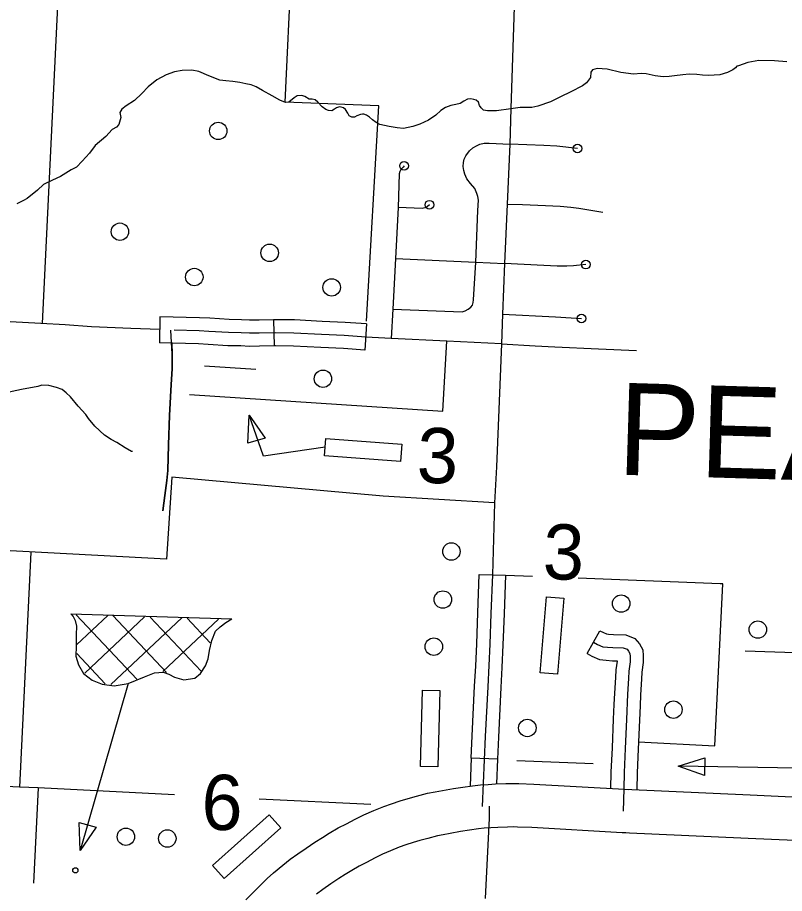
# Model space of a CAD drawing. Extents: x 653372 to 905732, y 627442 to 787275.
# Drawn here: x 679957 to 684356, y 774006 to 779033 of the extents above; entities that cross this region are included whole.
import ezdxf

# ---------------------------------------------------------------- set-up
doc = ezdxf.new("R2010")
doc.units = 0
for name, color, linetype in [('10', 7, 'Continuous'), ('31', 7, 'Continuous'), ('32', 7, 'Continuous'), ('33', 7, 'Continuous'), ('34', 7, 'Continuous'), ('35', 7, 'Continuous'), ('4', 7, 'Continuous'), ('45', 7, 'Continuous'), ('5', 7, 'Continuous'), ('56', 7, 'Continuous'), ('57', 7, 'Continuous'), ('6', 7, 'Continuous')]:
    doc.layers.add(name, color=color, linetype=linetype)

msp = doc.modelspace()

# ---------------------------------------------------------------- linework, layer by layer
at = {"layer": '10'}
for points in [[(681267.1, 773968.3), (681325, 774029.1), (681389.3, 774092.1), (681425.8, 774123.9), (681478.6, 774168.1), (681521.4, 774201.8), (681564.1, 774232.3), (681612.1, 774265.9), (681661.5, 774299.7), (681706, 774327.7), (681744.7, 774350.9), (681795.4, 774381.5), (681843.4, 774405.8), (681893.7, 774432.5), (681943.7, 774457.4), (682000.1, 774482.2), (682057.2, 774504.6), (682101.5, 774520.9), (682151.1, 774537.3), (682198.4, 774551.2), (682246, 774563.4), (682309.1, 774580.4), (682352.7, 774589), (682395.1, 774596.1), (682458, 774607.4), (682511.5, 774615.3), (682567.1, 774624.2), (682613.2, 774629.3), (682657.3, 774631.3), (682698.4, 774634), (682758.1, 774636.2), (682799, 774637.6), (682832.3, 774636.6), (682918.8, 774633.2), (683438.8, 774603.7), (683460.1, 774602.5)], [(683438.8, 774603.7), (684159.3, 774571.5), (684560.8, 774553.4), (684637.6, 774550.3), (684786.5, 774543.4), (685475.2, 774510.9), (685864.7, 774495), (686050.4, 774486.1), (686088.4, 774484), (686221.2, 774477.5), (686785.6, 774455.5), (687265.9, 774433.2)], [(683446, 774352.9), (683424.7, 774354.1), (682906.8, 774383.5), (682823.7, 774386.8), (682799.4, 774387.5), (682767, 774386.4), (682711.3, 774384.3), (682671.2, 774381.7), (682632.5, 774379.9), (682600.5, 774376.4), (682549.7, 774368.2), (682498.3, 774360.6), (682437.7, 774349.8), (682397.6, 774343.1), (682366, 774336.8), (682309.7, 774321.6), (682264.7, 774310.1), (682225.5, 774298.5), (682183.8, 774284.9), (682146.1, 774270.9), (682096.1, 774251.3), (682049.8, 774230.9), (682008.1, 774210.2), (681958.6, 774183.9), (681916.5, 774162.5), (681873.5, 774136.6), (681836.9, 774114.7), (681798.8, 774090.7), (681754.4, 774060.3), (681708.4, 774028.1), (681671.5, 774001.8)], [(687259.3, 774183.3), (686774.9, 774205.8), (686210.2, 774227.8), (686075.6, 774234.4), (686037.7, 774236.4), (685853.6, 774245.2), (685464.2, 774261.1), (684774.8, 774293.6), (684626.7, 774300.6), (684550.1, 774303.6), (684148.2, 774321.7), (683424.7, 774354.1)]]:
    msp.add_lwpolyline(points, dxfattribs=at)
at = {"layer": '31'}
for p, q in [((682605.6, 775837.2), (682755.5, 775831.8)), ((682584.7, 775310.8), (682584.7, 775310.8)), ((682709.3, 774776.4), (682559.5, 774782.7))]:
    msp.add_line(p, q, dxfattribs=at)
for points in [[(682584.7, 775310.8), (682591.4, 775439.1), (682597.6, 775616), (682605.6, 775837.2)], [(682680.5, 775834.5), (682672.5, 775613.3), (682666.3, 775435.8), (682653.6, 775191.5), (682639.7, 774906.8), (682622.8, 774504.6)], [(682755.5, 775831.8), (682747.5, 775610.6), (682741.2, 775432.5), (682734.5, 775303)], [(682559.5, 774782.7), (682564.8, 774910.2), (682578.7, 775195.3), (682584.7, 775310.8)], [(682734.5, 775303), (682728.5, 775187.8), (682714.7, 774903.4), (682709.3, 774776.4)], [(682559.5, 774782.7), (682552.7, 774622.7)], [(682709.3, 774776.4), (682703.3, 774634.2)]]:
    msp.add_lwpolyline(points, dxfattribs=at)
at = {"layer": '32'}
for p, q in [((681425.2, 777298.5), (681428, 777148.5)), ((681959.3, 777274.2), (681948.6, 777124.6))]:
    msp.add_line(p, q, dxfattribs=at)
for points in [[(681425.2, 777298.5), (681342, 777296.9), (681287.7, 777295.9), (681241.8, 777298.2), (681169.7, 777299.4), (681059.1, 777306.7), (681000.8, 777309.9), (680773.7, 777315.3), (680770.4, 777165.4)], [(681959.3, 777274.2), (681835.4, 777283), (681704, 777288.8), (681544.9, 777297.2), (681435.9, 777298.7), (681425.2, 777298.5)], [(680790.8, 776201.8), (680801.8, 776289.2), (680813.8, 776376.8), (680818.6, 776433.2), (680823.1, 776580.7), (680828.1, 776749.5), (680837.6, 776926.1), (680843.5, 777015.9), (680844, 777102.8), (680840.7, 777168.9), (680836.6, 777239.1)], [(681953.9, 777199.4), (681831.1, 777208.2), (681700.4, 777213.9), (681542.5, 777222.3), (681436.2, 777223.6), (681343.4, 777221.9), (681286.5, 777220.9), (681239.3, 777223.2), (681166.6, 777224.5), (681054.6, 777231.8), (680997.9, 777235), (680855.3, 777238.4)], [(681428, 777148.5), (681344.8, 777146.9), (681285.3, 777145.8), (681236.8, 777148.2), (681163.5, 777149.5), (681050.1, 777157), (680994.9, 777160), (680770.4, 777165.4)], [(681948.6, 777124.6), (681826.8, 777133.3), (681696.7, 777139), (681540, 777147.3), (681436.4, 777148.6), (681428, 777148.5)]]:
    msp.add_lwpolyline(points, dxfattribs=at)
at = {"layer": '33'}
for points in [[(682827.2, 779741.7), (682815.8, 779387.1), (682786.8, 778511), (682781.6, 778306.3), (682766.2, 777961.8), (682750.5, 777622.1), (682739, 777329.8), (682733.1, 777161), (682704.8, 776454.9), (682693.5, 776247.5), (682680.5, 775834.5)], [(682109.3, 777360.1), (682507.4, 777344.7), (682525.3, 777349.4), (682541.5, 777359.5), (682556.9, 777371.5), (682566, 777381.8), (682570.9, 777396.7), (682571.4, 777412.6), (682584.9, 777629.7), (682596.9, 777925.6), (682600, 777985.6), (682597.1, 778006), (682591.8, 778023), (682579, 778051), (682554.3, 778080.9), (682534.8, 778108), (682522.3, 778134.9), (682515.9, 778154.6), (682513, 778178.5), (682515.5, 778201.4), (682519.6, 778219.9), (682529, 778239.9), (682548.4, 778267.6), (682568.4, 778285.6), (682590, 778297.3), (682607.9, 778306.5), (682632.9, 778312.8), (682662, 778312.9), (682781.6, 778306.3)], [(683169.3, 778281.9), (683050.4, 778294.3), (682975.4, 778299.2), (682878.3, 778303), (682781.6, 778306.3)], [(682173.7, 778181.6), (682168.2, 778174.7), (682155.4, 778161), (682149.8, 778149.6), (682146.7, 778135.6), (682140, 777942.9), (682124.8, 777649.9), (682109.3, 777360.1), (682100.7, 777190.5)], [(682319.1, 777958.9), (682308.1, 777949.3), (682293.7, 777940.9), (682276.9, 777937.9), (682140, 777942.9)], [(682766.2, 777961.8), (682852.7, 777959.2), (682984.7, 777954.4), (683070.3, 777950), (683130.7, 777944.7), (683176.7, 777938.5), (683314.3, 777916.2)], [(682124.8, 777649.9), (682584.9, 777629.7), (682750.5, 777622.1)], [(683216.9, 777615), (683146.8, 777607.4), (683107, 777605.9), (683053.1, 777605.7), (682975.4, 777609), (682750.5, 777622.1)], [(682739, 777329.8), (683042.6, 777315.2), (683191.7, 777305.4)]]:
    msp.add_lwpolyline(points, dxfattribs=at)
for centre in [(682173.7, 778181.6), (682319.1, 777958.9), (683216.9, 777615), (683191.7, 777305.4)]:
    msp.add_circle(centre, 25, dxfattribs=at)
at = {"layer": '34'}
for points in [[(680772.1, 777242), (680606.4, 777249.2), (680381.1, 777258.5), (680230.5, 777269.5), (680089.8, 777276.2), (679913.4, 777286.3), (679757.3, 777293.5), (679569.9, 777304.8), (679481.4, 777308.3), (679447.3, 777309.3), (679400.5, 777306.6), (679366.2, 777301.1), (679330.1, 777292.5), (679205.2, 777264.4), (679092.8, 777235.2), (679023.1, 777218.6), (678986.2, 777211.5), (678952.6, 777205.2), (678922.4, 777202.1), (678890.6, 777198.9), (678860.4, 777197.4), (678798.5, 777196.8), (678766.8, 777199.4)], [(682733.1, 777161), (682419.8, 777175.7), (682100.7, 777190.5), (681953.9, 777199.4)], [(680841, 777163.7), (680844, 777102.8), (680843.5, 777015.9), (680837.6, 776926.1), (680828.1, 776749.5), (680823.1, 776580.7), (680818.6, 776433.2), (680813.8, 776376.8), (680801.8, 776289.2), (680790.8, 776201.8)], [(682733.1, 777161), (682926.8, 777148.1), (683039.5, 777143.6), (683289.5, 777132.4), (683507.1, 777121.2)], [(682641.4, 773977.5), (682664.1, 774437), (682664.1, 774486.9), (682663.2, 774506.4)]]:
    msp.add_lwpolyline(points, dxfattribs=at)
at = {"layer": '35'}
for points in [[(684369.4, 778778.2), (684298.8, 778784.6), (684209.1, 778785.6), (684145.8, 778775.4), (684092.5, 778755.4), (684083, 778754), (684074.9, 778743.9), (684059.5, 778733.1), (684028.8, 778717.6), (683986.2, 778705.1), (683919.6, 778700.2), (683885.1, 778702.1), (683853.3, 778705.6), (683808.5, 778707.8), (683773, 778703.7), (683724.5, 778699.1), (683694.2, 778694.9), (683659.6, 778693.3), (683614, 778699), (683562.6, 778710.9), (683534.2, 778712.6), (683490.6, 778708.8), (683418.3, 778717), (683338.7, 778736.6), (683280.9, 778740.1), (683255.7, 778733.1), (683245.9, 778720.4), (683243.2, 778688.6), (683220.7, 778658.2), (683196.9, 778641.6), (683130.3, 778606.5), (683071.6, 778577.2), (683013, 778549.6), (682941.8, 778523.7), (682907.1, 778516.1), (682839.4, 778516.8), (682786.8, 778509.5)], [(680808.8, 778703.9), (680754.8, 778675.7), (680705.3, 778636.2), (680670.4, 778596.2), (680628.3, 778556.5), (680579.1, 778527.2), (680555.1, 778507.4), (680544.2, 778488.7), (680549.2, 778459.3), (680537.8, 778420.1), (680524.1, 778404.4), (680498.8, 778390.5), (680462.5, 778350.6), (680402.4, 778298.2), (680370.3, 778253.8), (680327.9, 778208.2), (680294.7, 778174), (680265, 778158.8), (680202.4, 778121.2), (680156.4, 778100.6), (680105.8, 778074.3), (680071.2, 778041.6), (680012.7, 777995.1), (679990.3, 777982.6), (679951.7, 777963.2)], [(682786.8, 778509.5), (682705, 778496.8), (682653.2, 778497.5), (682630, 778500.8), (682615.8, 778514.1), (682605.9, 778529.1), (682600.4, 778546.6), (682587.8, 778559), (682575, 778562.9), (682557.8, 778566.8), (682538.7, 778563.9), (682516, 778552.5), (682496.6, 778539.3), (682471.4, 778534.9), (682442.7, 778528), (682411.3, 778516.8), (682384, 778498.7), (682355.6, 778472.8), (682314.2, 778444.6), (682263.5, 778421.1), (682223.4, 778408.5), (682171.3, 778397.1), (682133.4, 778400.9), (682087.5, 778407.4), (682035.2, 778419.4), (682013.1, 778430.4), (681992.1, 778446.5), (681976.1, 778460.8), (681957.5, 778472.6), (681943.1, 778479.1), (681935.2, 778479.3), (681923.9, 778476.2), (681903.8, 778468.2), (681888.9, 778460.9), (681875.1, 778460.4), (681859, 778469.5), (681850.8, 778483.6), (681837.6, 778504.7), (681826.7, 778514.5), (681813.1, 778519.3), (681802.7, 778520.4), (681787, 778515.7), (681774.7, 778507.5), (681759.7, 778498.4), (681740.9, 778499), (681725.4, 778504.6), (681704.3, 778520.8), (681678.3, 778546.6), (681664.9, 778560), (681646.1, 778564), (681628.9, 778564.5), (681604.2, 778579.1), (681588.1, 778585.6), (681560.4, 778583), (681543.9, 778573.1), (681512.1, 778548.2), (681493, 778545.3), (681461.5, 778558.3), (681416.5, 778583), (681362.2, 778614.8), (681324.9, 778635.8), (681296.7, 778647), (681266.7, 778653.1), (681231.5, 778660.2), (681191.7, 778665.7), (681152.1, 778670.3), (681116.8, 778674), (681053.7, 778698.3), (680996.6, 778724.2), (680957.1, 778730.6), (680900.1, 778728.8), (680856.8, 778721.5), (680808.8, 778703.9)], [(680615.2, 776542.8), (680610.9, 776543.1), (680573.8, 776564.1), (680525.6, 776594.8), (680493.6, 776610.4), (680454.6, 776635.7), (680399.7, 776688.6), (680363.3, 776732.6), (680349.3, 776754), (680304.7, 776803.5), (680260.3, 776856.1), (680235.9, 776879.9), (680212.4, 776898.4), (680179.2, 776909.8), (680136.7, 776921.6), (680095.9, 776923.9), (680072.7, 776916.2), (679978.4, 776898.9), (679882.5, 776876.6)]]:
    msp.add_lwpolyline(points, dxfattribs=at)
msp.add_circle((683169.3, 778281.9), 25, dxfattribs=at)
at = {"layer": '4'}
for points in [[(680857.9, 774571.9), (680074.7, 774611.2), (679967.9, 774616.4), (679348.3, 774646.5)], [(681982.7, 774515.5), (681342, 774547.6)]]:
    msp.add_lwpolyline(points, dxfattribs=at)
at = {"layer": '45'}
msp.add_line((683223.8, 775382.9), (683296.9, 775514), dxfattribs=at)
for points in [[(683296.9, 775514), (683317.2, 775502.6), (683335, 775494.9), (683347.4, 775493.2), (683374.9, 775491.6), (683446.5, 775490.6), (683498.5, 775470), (683525.3, 775438.7), (683542.7, 775403.6), (683545.1, 775369.4), (683546.1, 775330.7), (683538.8, 775275.4), (683536.6, 775235.5), (683530.8, 775146.4), (683527.9, 775082.7)], [(683260.4, 775448.5), (683283.9, 775435.3), (683314.6, 775421.9), (683340.3, 775418.5), (683372.2, 775416.7), (683431.7, 775415.8), (683453.6, 775407.1), (683462.2, 775397.1), (683468.9, 775383.6), (683470.1, 775365.8), (683471, 775334.6), (683464.1, 775282.4), (683461.7, 775240.1), (683455.9, 775150.5), (683449.3, 775003.5), (683442.1, 774838), (683435.7, 774699.6), (683433.7, 774605.5), (683431.7, 774478.9)], [(683223.8, 775382.9), (683250.6, 775368), (683294.3, 775349), (683333.1, 775343.8), (683369.5, 775341.7), (683395.8, 775341.3), (683395.8, 775338.6), (683389.4, 775289.4), (683386.8, 775244.6), (683381, 775154.6), (683378.1, 775089.4)], [(683378.1, 775089.4), (683374.3, 775006.8), (683367.1, 774841.4), (683360.7, 774702.1), (683358.8, 774608.3)], [(683527.9, 775082.7), (683524.2, 775000.2), (683517, 774834.7), (683510.6, 774697.1), (683508.7, 774600.6)]]:
    msp.add_lwpolyline(points, dxfattribs=at)
at = {"layer": '5'}
for points in [[(680220.5, 779815.4), (680097.1, 777276.6)], [(680033.4, 775965.4), (679967.9, 774616.4)], [(680074.7, 774611.2), (680048.1, 774065.3)]]:
    msp.add_lwpolyline(points, dxfattribs=at)
at = {"layer": '56'}
for p, q in [((681278.6, 776590.4), (681285.4, 776751.6)), ((681285.4, 776751.6), (681376.6, 776618.6)), ((681376.6, 776618.6), (681278.6, 776590.4)), ((683745.9, 774735.4), (683899.6, 774784)), ((683899.6, 774784), (683898.1, 774682)), ((683898.1, 774682), (683745.9, 774735.4))]:
    msp.add_line(p, q, dxfattribs=at)
for points in [[(681028.5, 777033.9), (681322.7, 777015.6)], [(681721.7, 776566.6), (681367.6, 776515), (681285.4, 776751.6)], [(684471.3, 775386.6), (684431.5, 774724.8), (683745.9, 774735.4)], [(684131.3, 775397.4), (684811.3, 775375.7)], [(682820.6, 774769.4), (683258.2, 774751.3)]]:
    msp.add_lwpolyline(points, dxfattribs=at)
for points in [[(681718, 776516.7), (681725.4, 776616.5), (682161.7, 776584.3), (682154.4, 776484.6)], [(682991.6, 775708.3), (683091.2, 775699.8), (683054.2, 775263.9), (682954.5, 775272.3)], [(682279, 775172.5), (682379, 775170), (682368.2, 774732.7), (682268.2, 774735.1)], [(681141, 774091.8), (681074.4, 774166.4), (681400.7, 774457.8), (681467.3, 774383.2)]]:
    msp.add_lwpolyline(points, close=True, dxfattribs=at)
for centre in [(681107.8, 778382.3), (680543.9, 777803.9), (681403.1, 777682.5), (680970.6, 777543.7), (681758.7, 777484.2), (681708.6, 776959.8), (682445.4, 775968.4), (682396.4, 775692.7), (683419.4, 775669.5), (684203.3, 775520.3), (682344.6, 775422.2), (683719.2, 775060.6), (682881.1, 774955.6), (680578.1, 774331.1), (680815.7, 774321.1)]:
    msp.add_circle(centre, 50, dxfattribs=at)
at = {"layer": '57'}
for p, q in [((680262.3, 775610.5), (681185.9, 775582.8)), ((680641.5, 775235.4), (680292.8, 775605.7)), ((680295, 775432), (680474.1, 775600.6)), ((680341.7, 775269.9), (680685, 775593.1)), ((680492.2, 775205.5), (680898.7, 775588.3)), ((680810.9, 775274.3), (680503.7, 775600.5)), ((681010.4, 775281.2), (680718, 775591.7)), ((680790.4, 775280.4), (681108.8, 775580.2)), ((681062.1, 775445.1), (680929.6, 775585.8)), ((680460, 775209.3), (680296.7, 775382.7)), ((680316.7, 774252.6), (680310, 774413.7)), ((680310, 774413.7), (680408, 774385.5)), ((680408, 774385.5), (680316.7, 774252.6))]:
    msp.add_line(p, q, dxfattribs=at)
for points in [[(680262.3, 775610.5), (680275, 775595.6), (680286.8, 775573.2), (680294, 775539.8), (680292.6, 775490.1), (680292, 775425.2), (680290.2, 775367.3), (680305.4, 775318.5), (680335.6, 775267.8), (680384.2, 775230.5), (680441.5, 775206.7), (680511.7, 775197.6), (680592.1, 775210.4), (680685.8, 775249), (680743.2, 775272.2), (680791.6, 775274.9), (680824.4, 775264.2), (680857, 775246.7), (680910.5, 775232.6), (680972.9, 775241.8), (681006.8, 775268.4), (681035.8, 775313.1), (681049.4, 775352.8), (681057.7, 775399.5), (681070.6, 775458.5), (681091.5, 775511.7), (681118.5, 775535.8), (681152.4, 775561), (681185.9, 775582.8)], [(680592.1, 775210.4), (680316.7, 774252.6)]]:
    msp.add_lwpolyline(points, dxfattribs=at)
msp.add_circle((680288.3, 774138.2), 15, dxfattribs=at)
at = {"layer": '6'}
for points in [[(681959, 777290.2), (682028.3, 778526.7), (681492.7, 778547.1), (681527.3, 779322), (682042.7, 779301.2), (682066.3, 779767.9)], [(680942.4, 776868.9), (682395.6, 776774.4), (682419.8, 777175.7)], [(680841.1, 776395.7), (680812, 775923.8), (678730.1, 776035), (678765.5, 777124.4)], [(682693.5, 776247.5), (682054.6, 776286), (680841.1, 776395.7)], [(682910.1, 775825.4), (682755.4, 775831.5)], [(683987.7, 775782.6), (683172.4, 775815)], [(683518.8, 774875.7), (683956.9, 774853.8), (684001.6, 775782.1), (683987.7, 775782.6)]]:
    msp.add_lwpolyline(points, dxfattribs=at)

# ---------------------------------------------------------------- texts
at = {"layer": '56'}
for s, p in [('3', (682244.6, 776364.1)), ('3', (682967.1, 775811)), ('6', (681008.1, 774373.8))]:
    msp.add_text(s, height=316.8, rotation=358.28, dxfattribs=at).set_placement(p)
at = {"layer": '6'}
msp.add_text('PEA RIDGE', height=528, rotation=358.28, dxfattribs=at).set_placement((683392.6, 776409.8))

doc.saveas('drawing.dxf')
